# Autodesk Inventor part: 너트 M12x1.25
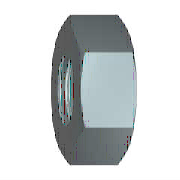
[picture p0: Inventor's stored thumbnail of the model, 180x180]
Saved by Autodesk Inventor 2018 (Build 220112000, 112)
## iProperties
IsCustomPart: 1
Created: 2012-02
Part Number: 너트 M12x1.25
Material: 강철, 연강
Description: 6각 너트
Document SubType Name: Modeling
Standard: KS B 1012
Designer: mduedu
Standards Organization: KS
Language: ko-KR
Size Designation: M12x1.25
Categories: <MemberInstance><Categories><Category DisplayName="조임쇠" InternalName="e4da775c-781d-43d5-af7c-5136215cf5a6" Mnemonic="FSTN"><Category DisplayName="너트" InternalN
Density: 1 g/cm^3
Appearance: 강철
Author: mduedu
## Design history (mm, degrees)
sketch "스케치1"
  geometry: L1 (-10.97, 0)-(-5.485, 9.5); L2 (-5.485, 9.5)-(5.485, 9.5); L3 (5.485, 9.5)-(10.97, 0); L4 (10.97, 0)-(5.485, -9.5); L5 (5.485, -9.5)-(-5.485, -9.5); L6 (-5.485, -9.5)-(-10.97, 0); 2 further points
  constraints: 12 end point, 1 coincident, 1 horizontal, 11 other
  dimensions: "d0" = 21.93931 distance of L3.end L1.start (= 1.1547 x SW)
extrude "본체" new body sketch "스케치1" distance "d1" = 10 (= KOH); taper "d2" = 0 deg
sketch "스케치2"
  geometry: L1 (0, 5.485)-(0, 10.97) reference; L2 (0, 10.97)-(10, 10.97) reference; L3 (10, 5.485)-(10, 10.97) reference; L4 (-2, 0)-(12, 0) reference; L5 (0.849, 10.97)-(0, 9.5); L6 (9.151, 10.97)-(10, 9.5)
  constraints: 4 end point, 4 point on line
  dimensions: "d3" = 30 deg angle of L1 L5 (= ANG1); "d4" = 30 deg angle of L3 L6 (= ANG2); "d5" = 19 diameter of L5.end L4 (= SW0); "d6" = 19 diameter of L6.end L4 (= SW01)
revolve "모따기1" sketch "스케치2" stored, may be unused: angle "d7" = 90 deg
sketch "스케치3"
  geometry: A1 r 9.5 centre (0, 0) between (-4.75, -8.227) and (4.75, -8.227) reference; 1 further point
  constraints: 1 coincident
hole "스레드" sketch "스케치3" at (0, 0) diameter "d25" = 10.647; stored, may be unused: countersink angle "d29" = 82 deg, drill point angle "d31" = 118 deg; dims "d26" = 6, "d27" = 4, "d28" = 2, "d30" = 8
workaxis "Work Axis1"
workplane "Work Plane1"
body "Solid1"
chamfer "모따기2" distance "d8" = 0.67658 (= -0.5 x GD1 + 0.5 x NND); stored, may be unused: angle "d9" = 30 deg, second distance "d40" = 0.67658 (= -0.5 x GD1 + 0.5 x NND)
chamfer "모따기3" distance "d10" = 0.67658 (= -0.5 x GD1 + 0.5 x NND); stored, may be unused: angle "d11" = 30 deg, second distance "d41" = 0.67658 (= -0.5 x GD1 + 0.5 x NND)
other parameters: "ANG1" = 30 deg [user parameter; used in 1 equation term], "ANG2" = 30 deg [user parameter; used in 1 equation term], "NND" = 12 [user parameter; used in 4 equation terms], "KOH" = 10 [user parameter; used in 1 equation term], "SW" = 19 [user parameter; used in 4 equation terms], "SW0" = 19 (= SW) [user parameter; used in 1 equation term], "SW01" = 19 (= SW) [user parameter; used in 1 equation term], "GD1" = 10.64684 (computed from THREADDIA, PTC, TOA) [user parameter; used in 4 equation terms], "d13" = 0, "d14" = 0, "d39" = 0, "d42" = 0, "GUL" = 0.67658 (= 0.541266 x PTC) [user parameter], "TPU" = 8 (computed from PTC) [user parameter], "THREADDIA" = 12 [user parameter; used in 1 equation term], "TOA" = 30 deg [user parameter; used in 1 equation term], "PTC" = 1.25 [user parameter; used in 4 equation terms], "E0" = 21.945 (= 1.155 x SW) [user parameter], "GAL" = 0.67658 (= 0.541266 x PTC) [user parameter]
